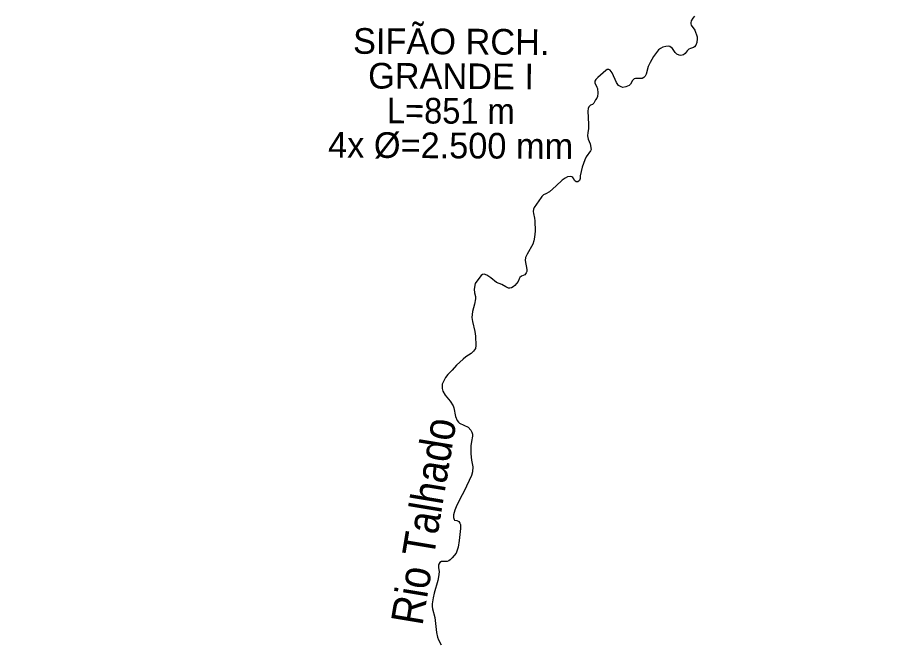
# Model space of a CAD drawing. Extents: x -1643653 to 4543381, y 1624270 to 13878484.
# Drawn here: x 614474 to 628142, y 8951330 to 8961099 of the extents above; entities that cross this region are included whole.
import ezdxf
from ezdxf.enums import TextEntityAlignment as Align

# ---------------------------------------------------------------- set-up
doc = ezdxf.new("R2010")
doc.units = 0
doc.header["$LTSCALE"] = 160
for name, color, linetype, lineweight in [('24', 7, 'Continuous', 25), ('50', 7, 'Continuous', 13), ('60', 7, 'Continuous', 13)]:
    doc.layers.add(name, color=color, linetype=linetype, lineweight=lineweight)
doc.layers.add('49', color=7, linetype='Continuous')

msp = doc.modelspace()

# ---------------------------------------------------------------- linework, layer by layer
at = {"layer": '24'}
for points in [[(625027.5, 8961119), (625000.9, 8961089), (624975.3, 8961048.8), (624966.1, 8961016.8), (624966.2, 8960999.8), (624973, 8960982.7), (625029.9, 8960900.7), (625064.6, 8960798.6), (625067, 8960768.6), (625061.1, 8960709.5), (625046, 8960671.4), (625027.5, 8960644.3), (625011.3, 8960634.2), (624961, 8960619.2), (624936.3, 8960606.1), (624912, 8960582), (624879.5, 8960536.9), (624854.3, 8960516.8), (624811.3, 8960509.7), (624784.5, 8960512.7), (624750.7, 8960527.7), (624725.6, 8960556.7), (624680, 8960618.7), (624640.1, 8960648.7), (624615.7, 8960653.7), (624577.3, 8960648.6), (624531.2, 8960635.5), (624496.8, 8960619.4)], [(624496.8, 8960619.4), (624466.5, 8960595.3), (624466.5, 8960595.3), (624418.2, 8960536.2), (624388.4, 8960493.1), (624334.1, 8960398.8), (624304.9, 8960334.7), (624271.6, 8960219.4), (624255.9, 8960184.4), (624237, 8960167.3), (624209.4, 8960152.2), (624177.8, 8960149.2), (624105.6, 8960150.1), (624084, 8960144), (624056.4, 8960117.9), (624029.7, 8960062.8), (624008.5, 8960040.7), (623952.6, 8960017.6), (623906.6, 8960011.5), (623879.7, 8960018.5), (623839.9, 8960041.5), (623809.1, 8960087.5), (623742.1, 8960236.6), (623708.6, 8960280.6), (623691, 8960291.6), (623663.5, 8960287.6), (623642.3, 8960274.5), (623518.1, 8960166.2), (623487.9, 8960132.1), (623473.9, 8960107), (623469.3, 8960080), (623503, 8960016.9), (623511.8, 8959991.9), (623518.8, 8959918.8), (623515.2, 8959871.7), (623503, 8959841.6), (623483.8, 8959814.6), (623458.3, 8959764.4), (623435.3, 8959743.4), (623405.8, 8959733.3), (623380.1, 8959708.2), (623370, 8959684.2), (623363, 8959639.1), (623374, 8959437.8), (623371.3, 8959365.7), (623362.7, 8959309.6), (623359.5, 8959254.5), (623367, 8959203.4), (623399.7, 8959131.4), (623414.8, 8959045.2), (623404.2, 8959022.2), (623338.3, 8958926.9), (623315, 8958880.8), (623272.9, 8958769.6), (623243.1, 8958633.3), (623241.6, 8958590.3), (623234, 8958561.2), (623207.1, 8958537.1), (623180.9, 8958538.1), (623154, 8958559.1), (623142.4, 8958588.1), (623129.2, 8958606.1), (623114.3, 8958616.1), (623091.3, 8958624.1), (623048.1, 8958618)], [(623048.1, 8958618), (623008.6, 8958598.9), (622961, 8958563.8), (622867, 8958474.5), (622765.3, 8958385.2), (622710.3, 8958350.1), (622672.6, 8958336), (622645.8, 8958310.9), (622635.8, 8958292.8), (622526.4, 8958139.4), (622516.5, 8958114.4), (622511.7, 8958078.3), (622515.3, 8958048.3), (622533.3, 8957971.2), (622537.7, 8957930.1), (622539.2, 8957771.9), (622532.6, 8957678.7), (622519.6, 8957617.6), (622503, 8957566.5), (622414.7, 8957413.1), (622392.8, 8957358), (622387.2, 8957313.9), (622413.1, 8957173.7), (622412, 8957144.7), (622401.3, 8957121.6), (622379.3, 8957091.6), (622329.5, 8957067.4), (622303.6, 8957046.4), (622292.3, 8957028.3), (622277.2, 8956988.2), (622224.7, 8956922.1), (622199.4, 8956902), (622173.6, 8956888.9), (622144.5, 8956882.9), (622124.1, 8956884.8), (622082.2, 8956903.8), (622023.4, 8956940.8)], [(622023.4, 8956940.8), (621940, 8956970.7), (621852.9, 8957044.7), (621852.9, 8957044.7), (621788.3, 8957084.6), (621747.1, 8957098.6), (621722, 8957094.5), (621699.9, 8957079.5), (621630.5, 8956993.2), (621609.1, 8956955.1), (621593, 8956869), (621597.7, 8956809.9), (621609.5, 8956752.8), (621610.3, 8956716.8), (621596.7, 8956635.6), (621564.2, 8956517.4), (621555.7, 8956425.2), (621563.4, 8956363.1), (621602.1, 8956205), (621612.3, 8956132.8), (621617.2, 8955989.6), (621609.4, 8955942.6), (621581.9, 8955900.4), (621546.5, 8955864.3), (621462.3, 8955810.1), (621421.6, 8955778), (621315.5, 8955681.7), (621248.5, 8955606.5), (621180.3, 8955539.2), (621144.2, 8955490.1), (621090.8, 8955387.9), (621089.6, 8955318.8), (621102.6, 8955276.7), (621141.2, 8955216.7), (621216.2, 8955123.7), (621263.9, 8955050.6), (621273.7, 8955018.6), (621298.4, 8954880.4), (621326.6, 8954818.3), (621344.8, 8954792.3), (621361.2, 8954778.3), (621494.9, 8954716.5), (621540.7, 8954668.5), (621556.5, 8954637.4), (621563.9, 8954607.4), (621564.5, 8954574.3), (621548.8, 8954491.2), (621540.9, 8954424.1), (621539.7, 8954301.9), (621548, 8954202.7), (621568.6, 8954096.6), (621562.7, 8954019.5), (621547, 8953964.4), (621433.8, 8953717.8), (621371.7, 8953602.5), (621309.6, 8953474.2), (621290.3, 8953424.1), (621271.3, 8953352), (621268.5, 8953307.9), (621278.3, 8953276.9), (621286.8, 8953268.9), (621318.5, 8953261.9), (621350.1, 8953247.9), (621369.2, 8953222.9), (621379.6, 8953197.9)], [(621379.6, 8953197.9), (621378.8, 8953137.8), (621359.7, 8952949.5), (621342.4, 8952846.3), (621307.8, 8952755.1), (621249.5, 8952681.9), (621219.1, 8952650.8), (621195, 8952631.7), (621171.1, 8952622.7), (621146.2, 8952620.6), (621100.1, 8952625.6), (621079.8, 8952621.5), (621057, 8952606.5), (621039.6, 8952581.4), (621035.3, 8952565.4), (621033.6, 8952527.3), (621045.1, 8952461.2), (621037.1, 8952383.1), (621025.7, 8952328), (620968.5, 8952127.6), (620952.3, 8952055.4), (620937.5, 8951961.3), (620936.1, 8951922.2), (620941.1, 8951883.2), (620980.3, 8951750), (621003, 8951516.7), (621017.4, 8951444.6), (621032.5, 8951402.6), (621077.7, 8951325.5)]]:
    msp.add_lwpolyline(points, dxfattribs=at)
at = {"layer": '60', "lineweight": 25}
msp.add_spline([(814781, 9009175.5), (814787.2, 9009173.4), (814796.9, 9009173.4), (814799.4, 9009172.4), (814805.1, 9009174.5), (814805.6, 9009176.5), (814811.7, 9009179.5), (814811.7, 9009179.5), (814801.5, 9009181), (814790.7, 9009181.5), (814784.1, 9009183.1), (814777.4, 9009185.1), (814778.4, 9009175.5)], degree=3, dxfattribs=at)

# ---------------------------------------------------------------- texts
at = {"layer": '49', "width": 0.9}
msp.add_text('Rio Talhado', height=500, rotation=80.538, dxfattribs=at).set_placement((621050.4, 8953212.3), align=Align.CENTER)
at = {"layer": '50'}
for s, p in [('SIFÃO RCH.', (621232.5, 8960526.2)), ('GRANDE I', (621229.3, 8959986.2)), ('4x Ø=2.500 mm', (621222.8, 8958906.2))]:
    msp.add_text(s, height=400, rotation=359.655, dxfattribs=at).set_placement(p, align=Align.CENTER)
at = {"layer": '50', "width": 0.95}
msp.add_text('L=851 m', height=400, rotation=359.655, dxfattribs=at).set_placement((621226, 8959446.2), align=Align.CENTER)

doc.saveas('drawing.dxf')
